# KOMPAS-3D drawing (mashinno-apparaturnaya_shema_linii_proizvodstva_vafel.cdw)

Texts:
  ОУП-02068108-260601-96-2010
  Машинно-аппаратурная  схема линии  производства вафель
  Игорь
  Слой 1
  Завернутые вафли
  Вафельное
  тесто
  Соль
  Сода
  Яичный желток
  Фосфатиды
  Начинка
  Вода
  Сахар
  Жир
  Эмульсия
  Ароматические
  и красящие
  вещества
  Вафельные
  обрезки
  отеки
  листы
  Саранов И.А.
  Рязанов А.Н.
  УП-02068108-260601-2010-
  Машинно-аппаратурная
  схема линии
  производства вафель
Dimensions and other numbers on the sheet: 1; 2; 3; 4; 5; 6; 7; 8; 9; 10; 11; 12; 13; 14; 15; 16; 17; 18; 19; 20; 21; 22; 23; 24; 25; 26; 27; 28; 29; 30; 31; 32; 33; 34; 35; 0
